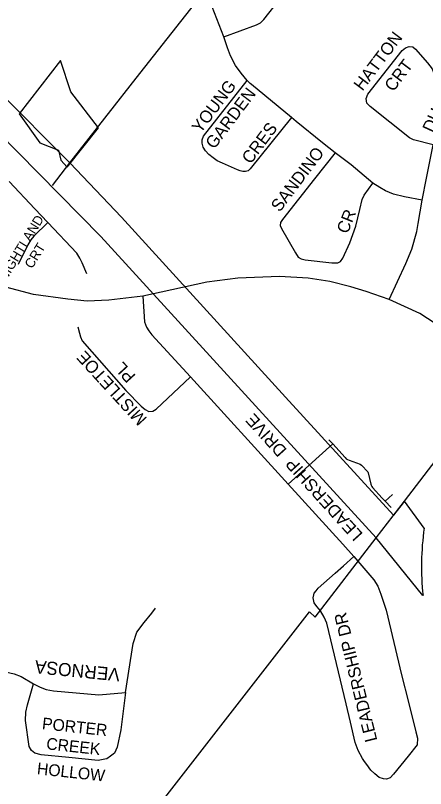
# Model space of a CAD drawing. Extents: x 586326 to 623965, y 4819854 to 4857850.
# Drawn here: x 598749 to 599283, y 4833487 to 4834491 of the extents above; entities that cross this region are included whole.
import ezdxf

# ---------------------------------------------------------------- set-up
doc = ezdxf.new("R2010")
doc.units = 0
for name, color, linetype in [('Hydro ROW', 7, 'Continuous'), ('Lots_Concessions', 7, 'Continuous'), ('Major Rds and Hwys', 7, 'Continuous'), ('Major Rds Lbls', 7, 'Continuous'), ('Minor Rd Lbls', 7, 'Continuous'), ('Minor Rds', 7, 'Continuous'), ('Park Outlines', 7, 'Continuous'), ('Private Rds', 7, 'Continuous'), ('Proposed Minor Rds', 7, 'Continuous'), ('Proposed Secondary Rds', 7, 'Continuous'), ('Secondary Rds Lbls', 7, 'Continuous')]:
    doc.layers.add(name, color=color, linetype=linetype)

msp = doc.modelspace()

# ---------------------------------------------------------------- linework, layer by layer
at = {"layer": 'Hydro ROW'}
for p, q in [((598820.1, 4834299.6), (598609.5, 4834510)), ((598860.2, 4834203.9), (598586.8, 4834481.1)), ((598887, 4834228.8), (598820.1, 4834299.6)), ((599100.6, 4833995.1), (598887, 4834228.8)), ((599111.7, 4833928.9), (598860.2, 4834203.9)), ((599240.8, 4833841.6), (599100.6, 4833995.1)), ((599218.2, 4833812.2), (599111.7, 4833928.9)), ((599255, 4833860), (599240.8, 4833841.6)), ((599280.7, 4833824.9), (599255, 4833860)), ((599279.2, 4833737.3), (599218.2, 4833812.2))]:
    msp.add_line(p, q, dxfattribs=at)
msp.add_arc((599637.2, 4833775.1), 359.9, 172.047, 186.0311, dxfattribs=at)
at = {"layer": 'Lots_Concessions'}
for p, q in [((598910.9, 4834415.5), (599113.1, 4834673.3)), ((598820.1, 4834299.6), (598910.9, 4834415.5)), ((598797.6, 4834270.1), (598820.1, 4834299.6)), ((599255, 4833860), (599560.4, 4834256.7)), ((599218.2, 4833812.2), (599255, 4833860)), ((599138.9, 4833709), (599218.2, 4833812.2)), ((598885.6, 4833400.1), (599131.8, 4833716)), ((599131.8, 4833716), (599138.9, 4833709))]:
    msp.add_line(p, q, dxfattribs=at)
at = {"layer": 'Major Rds and Hwys'}
for points in [[(599205.2, 4834132.4), (599185.3, 4834138.4), (599158.3, 4834145.4), (599129.9, 4834149.7), (599092.8, 4834151.8), (599038.4, 4834149.6), (598998.3, 4834144.6), (598952.8, 4834134.4), (598914.8, 4834126.2)], [(598914.8, 4834126.2), (598870.8, 4834120.9), (598842.5, 4834119.7), (598817.2, 4834122.1), (598772.8, 4834128.5), (598736.8, 4834138), (598705.7, 4834149.1), (598705.6, 4834149.1)], [(599235.3, 4834121.8), (599205.2, 4834132.4)], [(599375, 4834024.5), (599357.8, 4834042.7), (599338.2, 4834060.1), (599306.5, 4834083.5), (599275, 4834103.7), (599235.3, 4834121.8)]]:
    msp.add_lwpolyline(points, dxfattribs=at)
at = {"layer": 'Minor Rds'}
for points in [[(599020.3, 4834462.9), (599062.6, 4834478.7), (599067.9, 4834481.3), (599072.1, 4834485.6), (599157.3, 4834593.4), (599160.6, 4834598.4), (599161.9, 4834602.9), (599161.2, 4834606.8), (599159, 4834611.5), (599125, 4834645.2), (599120.3, 4834647), (599116.3, 4834646.9), (599111.2, 4834644.7), (599107, 4834640.4), (599029.6, 4834542.7), (599024.1, 4834537.7), (599019.5, 4834534.9), (598996, 4834525.8)], [(599020.3, 4834462.9), (598996, 4834525.8)], [(599050.5, 4834406.3), (599042.8, 4834415.8), (599035.6, 4834426), (599029.1, 4834438.5), (599024.9, 4834448.7), (599020.3, 4834462.9)], [(599292.4, 4834323), (599266.7, 4834329.2), (599261.6, 4834332), (599210.4, 4834372.5), (599206.2, 4834376.9), (599205.5, 4834382.8), (599207.5, 4834388.7), (599252.3, 4834445.5), (599256.7, 4834448.6), (599261.3, 4834450.4), (599266, 4834450.1), (599269.5, 4834446.9), (599285.1, 4834429.4), (599291.2, 4834421.4), (599295.7, 4834410)], [(598993.7, 4834333.9), (599050.5, 4834406.3)], [(599054.7, 4834402.6), (599050.5, 4834406.3)], [(599108.4, 4834358.2), (599056.4, 4834401.2), (599054.7, 4834402.6)], [(599108.4, 4834358.2), (599054.7, 4834291.5), (599051.7, 4834289.1), (599048.4, 4834288), (599044.8, 4834288.2), (599041.4, 4834289), (599038, 4834290.3)], [(599148.4, 4834325.6), (599114.2, 4834353.1), (599108.4, 4834358.2)], [(599038, 4834290.3), (599018.5, 4834298.9), (599011.8, 4834302.2), (599006.4, 4834305.8), (599000.8, 4834310.1), (598996.5, 4834314.8), (598993.3, 4834319.8), (598992, 4834324.9), (598992.1, 4834329.5), (598993.7, 4834333.9)], [(599165, 4834312.3), (599148.4, 4834325.6)], [(599165, 4834312.3), (599138.2, 4834278.6), (599096.5, 4834226), (599094.1, 4834221.8), (599093.6, 4834217.9), (599095.1, 4834213.9), (599113.5, 4834182.7), (599117.1, 4834176.9), (599120.8, 4834174.5), (599126.2, 4834173.3), (599160.6, 4834169.4), (599168.6, 4834169.7), (599172.1, 4834171.4), (599174.8, 4834175.5), (599184.1, 4834195.4), (599192, 4834217.2), (599197, 4834239), (599200.2, 4834251.9), (599202.9, 4834257.5), (599214, 4834273)], [(599214, 4834273), (599185.7, 4834296.7), (599165, 4834312.3)], [(598774.5, 4834239.8), (598741, 4834275.1)], [(599278, 4834251.1), (599255.3, 4834255.3), (599240.8, 4834258.8), (599230.6, 4834263), (599223.3, 4834267.3), (599214, 4834273)], [(598791.4, 4834221.9), (598774.5, 4834239.8)], [(598791.4, 4834221.9), (598773.2, 4834204.1), (598769.1, 4834199.2), (598765.2, 4834192.9), (598752.9, 4834167.4)], [(598842.1, 4834155.2), (598835.9, 4834169.3), (598833.1, 4834175.6), (598829.2, 4834182), (598791.4, 4834221.9)], [(598914.8, 4834126.2), (598917, 4834092.7), (598919.6, 4834086.1), (598922.6, 4834081), (598926.8, 4834075.8), (598976.8, 4834021.4)], [(598830.4, 4834086.5), (598832.6, 4834078.3), (598833.8, 4834073.5), (598836.2, 4834068.2), (598893, 4834003.5), (598912.6, 4833983.1), (598917.9, 4833979.1), (598922.8, 4833976.5), (598928, 4833976.6), (598932.1, 4833979.5), (598976.8, 4834021.4)], [(598976.8, 4834021.4), (599104, 4833881.9), (599174.8, 4833804.2), (599189.2, 4833788.1)], [(599145.9, 4833717.5), (599141.5, 4833722.5), (599141.2, 4833722.9), (599137.8, 4833728), (599136.4, 4833734.2), (599137.4, 4833738.4), (599137.9, 4833740.2), (599140.5, 4833743.5), (599143, 4833746.8), (599164.9, 4833766.4), (599175.7, 4833776.1), (599189.2, 4833788.1)], [(599189.2, 4833788.1), (599194.6, 4833781.8)], [(599194.6, 4833781.8), (599215.3, 4833757.6), (599220.6, 4833749.3), (599224.3, 4833739.2), (599231.2, 4833718.3), (599251.3, 4833634.4), (599260.2, 4833598.8)], [(599227.9, 4833499), (599222.4, 4833500.9), (599216.5, 4833505.5), (599211.6, 4833510.5), (599206.1, 4833517.6), (599203.2, 4833521.7), (599200.4, 4833525.8), (599195.1, 4833535.9), (599191.2, 4833546.5), (599185, 4833572.6), (599179.2, 4833596.7), (599154.1, 4833701.3), (599150.9, 4833709.3), (599145.9, 4833717.5)], [(598694.2, 4833641), (598734.8, 4833638.6), (598747.5, 4833635.7), (598756.9, 4833632.1), (598772.6, 4833622.7)], [(598865.5, 4833524.8), (598856.8, 4833523), (598818.7, 4833526.8), (598782.5, 4833530.5), (598774.6, 4833532.4), (598770.2, 4833535.9), (598767.1, 4833541.1), (598762.4, 4833575.1), (598762.9, 4833585.9), (598764.9, 4833595.4), (598772.6, 4833622.7)], [(598772.6, 4833622.7), (598781.2, 4833618.1), (598789.4, 4833615.4), (598798.6, 4833613.7), (598857.5, 4833608.3)], [(599260.2, 4833598.8), (599270, 4833560.1), (599272.1, 4833551.8), (599271.6, 4833543.3), (599259.9, 4833528.8), (599241, 4833505.2), (599236.6, 4833500.3), (599232, 4833498.6), (599227.9, 4833499)]]:
    msp.add_lwpolyline(points, dxfattribs=at)
at = {"layer": 'Park Outlines'}
msp.add_lwpolyline([(598753.9, 4834363), (598780.9, 4834325.5), (598805.1, 4834315.8), (598808.2, 4834302.7), (598816.4, 4834293.6), (598857.2, 4834344.9), (598821.1, 4834391.7), (598807.8, 4834432.4)], close=True, dxfattribs=at)
at = {"layer": 'Private Rds'}
for points in [[(599156.8, 4833939.5), (599161.8, 4833934.3)], [(599104, 4833881.9), (599161.8, 4833934.3)], [(599161.8, 4833934.3), (599178.1, 4833916.6), (599179.5, 4833915.1), (599181, 4833914.1), (599183.1, 4833913.1), (599197.5, 4833907.9), (599199.3, 4833906.8), (599207.5, 4833897.9), (599207.9, 4833896.9), (599211.5, 4833881.8), (599211.9, 4833880.7), (599212.7, 4833879), (599213.8, 4833877.6), (599226.2, 4833864), (599229.9, 4833860.1), (599230, 4833860)], [(599230, 4833860), (599239.5, 4833868.4)], [(599230, 4833860), (599237.7, 4833851.5)]]:
    msp.add_lwpolyline(points, dxfattribs=at)
at = {"layer": 'Proposed Minor Rds'}
for points in [[(598892.4, 4833611.2), (598902.5, 4833674.8), (598907.2, 4833689.9), (598916.8, 4833702.2), (598926.5, 4833714.6), (598931.6, 4833721.1)], [(598857.5, 4833608.3), (598892.4, 4833611.2)], [(598892.4, 4833611.2), (598886.3, 4833563), (598881.6, 4833540.4), (598877.9, 4833532.4), (598873, 4833528.7), (598868, 4833525.3), (598865.5, 4833524.8)]]:
    msp.add_lwpolyline(points, dxfattribs=at)
at = {"layer": 'Proposed Secondary Rds'}
for points in [[(599278, 4834251.1), (599283.8, 4834279.4), (599292.4, 4834323)], [(599272.9, 4834220.4), (599272.9, 4834220.7), (599278, 4834251.1)], [(599235.3, 4834121.8), (599257.1, 4834168.7), (599264.6, 4834187.4), (599271.1, 4834210.3), (599272.9, 4834220.4)]]:
    msp.add_lwpolyline(points, dxfattribs=at)

# ---------------------------------------------------------------- texts
at = {"layer": 'Major Rds Lbls'}
for s, height, rotation, p in [('CHINGUACOUSY        RD', 49.998, 135.2178, (599589.5, 4834328.2)), ('MISTLETOE', 15.99, 132.5237, (598921.3, 4833967.3)), ('PL', 15.99, 132.5237, (598906.5, 4834022.9))]:
    msp.add_text(s, height=height, rotation=rotation, dxfattribs=at).set_placement(p)
at = {"layer": 'Minor Rd Lbls'}
for s, height, rotation, p in [('HATTON', 15.99, 52.9375, (599200.5, 4834391.9)), ('CRT', 15.99, 52.9375, (599240.6, 4834390.8)), ('YOUNG', 15.99, 52.9375, (598990, 4834336.8)), ('GARDEN', 15.99, 52.9375, (599007.8, 4834316.2)), ('CRES', 15.99, 52.9375, (599055, 4834296.8)), ('SANDINO', 15.99, 52.9375, (599092.9, 4834234.5)), ('NIGHTLAND', 12.46, 58.4055, (598736.4, 4834144.5)), ('CR', 15.99, 68.4037, (599181.2, 4834206.2)), ('CRT', 12.46, 58.4055, (598770.9, 4834161)), ('LEADERSHIP  DRIVE', 15.991, 132.1076, (599201.9, 4833817.3)), ('LEADERSHIP DR', 15.991, 103.7692, (599220, 4833549.2)), ('VERNOSA', 16.98, 174.4117, (598885.9, 4833642.6)), ('PORTER', 15.29, 353.8221, (598783.3, 4833563.8)), ('CREEK', 15.29, 353.8221, (598788.8, 4833537.6)), ('HOLLOW', 15.29, 353.8221, (598776.7, 4833505.2))]:
    msp.add_text(s, height=height, rotation=rotation, dxfattribs=at).set_placement(p)
at = {"layer": 'Secondary Rds Lbls'}
msp.add_text('DUSK', height=15.99, rotation=65.4934, dxfattribs=at).set_placement((599292.3, 4834337.6))

doc.saveas('drawing.dxf')
